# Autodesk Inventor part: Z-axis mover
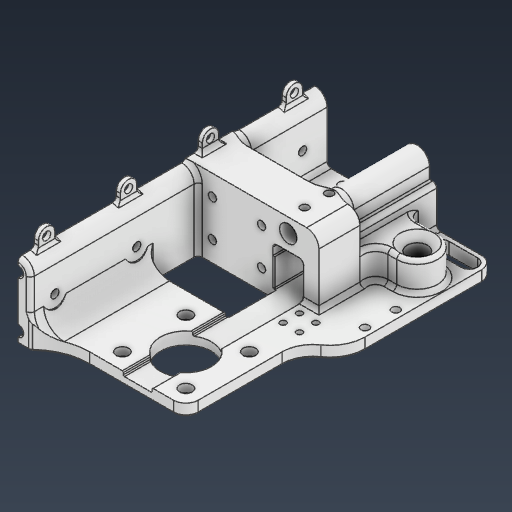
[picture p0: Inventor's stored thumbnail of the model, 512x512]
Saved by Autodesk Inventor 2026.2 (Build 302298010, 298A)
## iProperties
Created: 2026-04
Part Number: Z-axis mover
Material: ABS 플라스틱
Document SubType Name: Modeling
Designer: work
Density: 1.06 g/cm^3
Appearance: 매끄러움 - 흰색
Mass: 127.398 g
Surface Area: 474.299 cm^2
Volume: 120.186 cm^3
Author: work
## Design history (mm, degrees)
sketch "스케치1"
  geometry: L1 (0, 0)-(8, 0); L2 (0, 0)-(0, 8); L3 (0, 0)-(-8, 0); L4 (0, 0)-(0, -8); L5 (0, 0)-(50, 0); L6 (0, 0)-(-50, 0); L7 (0, 0)-(0, 50); L8 (25, 0)-(25, -380); L9 (-25, 0)-(-25, -380); L10 (-25, 0)-(-25, 70); L11 (25, -380)-(-25, -380); L12 (25, 0)-(25, 0); L13 (25, 0)-(25, 120); L14 (-37.5, -395)-(37.5, -395); L15 (37.5, -395)-(37.5, -365); L16 (37.5, -365)-(-37.5, -365); L17 (-37.5, -365)-(-37.5, -395); L18 (-37.5, -395)-(37.5, -365); L19 (37.5, -395)-(-37.5, -365); L20 (-62.5, 38)-(62.5, 38); L21 (62.5, 38)-(62.5, -38); L22 (62.5, -38)-(-62.5, -38); L23 (-62.5, -38)-(-62.5, 38); L24 (-62.5, 38)-(62.5, -38); L25 (62.5, 38)-(-62.5, -38); L26 (62.5, -25)-(-62.5, -25); L27 (17, 38)-(-17, 38); L28 (-17, 38)-(-17, 61); L29 (-17, 61)-(17, 61); L30 (17, 61)-(17, 38); L31 (-22, 60.236)-(-22, 100); L32 (-22, 100)-(-28, 100); L33 (-28, 100)-(-28, -380); L34 (-28, -380)-(-22, -380); L35 (-22, -380)-(-22, 100); L36 (-40, 38)-(40, 38); L37 (40, 38)-(40, 18); L38 (40, 18)-(-40, 18); L39 (-40, 18)-(-40, 38); C1 r 5.25 at (0, 0); C2 r 11.3 at (0, 0); C3 r 2 at (8, 0); C4 r 2 at (0, 8); C5 r 2 at (-8, 0); C6 r 2 at (0, -8); C7 r 4.4 at (50, 0); C8 r 4.4 at (-50, 0); C9 r 4 at (0, 50); 7 further points
  constraints: 78 end point, 12 midpoint, 10 parallel, 9 centre point, 9 coincident, 8 horizontal, 6 perpendicular, 6 point on line, 5 vertical, 2 symmetric about line, 1 collinear, 22 other
  dimensions: "d0" = 10.5 diameter of C1; "d1" = 22.6 diameter of C2; "d2" = 8 distance of L1.start L1.end; "d3" = 4 diameter of C3; "d6" = 360 deg dimension on C1.centre L1.end (derived); "d8" = 50 distance of L4.start L5.end; "d9" = 8.8 diameter of C7; "d10" = 50 distance of L4.start L7.end; "d11" = 8 diameter of C9; "d12" = 12 distance of point (0, 38) L7.end; "d15" = 450 distance of L9.end L10.end; "d16" = 25 distance from line of point (0, 0) L8; "d17" = 25 distance from line of L10 C1.centre; "d19" = 500 distance of L8.end L13.end; "d20" = 120 vertical distance of point (0, 0) L13.end; "d21" = 75 distance between parallel lines of L17 L15; "d22" = 30 distance of L14.end L15.end; "d23" = 125 distance between parallel lines of L23 L21; "d24" = 25 distance from line of point (0, 0) L26; "d25" = 340 distance between parallel lines of L16 L26 (derived); "d26" = 34 distance of L28.end L29.end; "d27" = 23 distance of L27.end L28.end; "d30" = 6 distance between parallel lines of L33 L35; "d31" = 80 distance of L37.end L38.end; "d32" = 20 distance of L36.end L37.end; "d60" = 30 distance of L10.end point (-25, 100)
  node "스케치 - 원형 패턴1" dims "d6" = 360 deg (derived)
extrude "돌출1" new body sketch "스케치1" distance "d33" = 6; taper "d34" = 0 deg
extrude "돌출2" join sketch "스케치1" distance "d35" = 4; taper "d36" = 0 deg
extrude "돌출3" join sketch "스케치1" distance "d37" = 38; taper "d38" = 0 deg
sketch "스케치2"
  geometry: L1 (102.5, 6)-(22.5, 6) reference; L2 (87.5, 6)-(87.5, 31); L3 (93.5, 6)-(93.5, 31); L4 (81.5, 31)-(81.5, 6); L5 (0, 0)-(125, 0) reference; L6 (62.5, 6)-(37.5, 6); L7 (37.5, 6)-(37.5, 31); L8 (37.5, 31)-(62.5, 31); L9 (62.5, 31)-(62.5, 6); L10 (30.5, 4)-(44.5, 4); L11 (44.5, 4)-(44.5, 18); L12 (44.5, 18)-(30.5, 18); L13 (30.5, 18)-(30.5, 4); L14 (30.5, 4)-(44.5, 18); L15 (44.5, 4)-(30.5, 18); L16 (44.5, -10.5)-(86.5, -10.5); L17 (86.5, -10.5)-(86.5, 32.5); L18 (86.5, 32.5)-(44.5, 32.5); L19 (44.5, 32.5)-(44.5, -10.5); L20 (44.5, -10.5)-(86.5, 32.5); L21 (86.5, -10.5)-(44.5, 32.5); L22 (47.5, 32.5)-(47.5, -10.5); L23 (37.5, 6)-(37.5, 31); L24 (43.5, 6)-(43.5, 31); L25 (31.5, 31)-(31.5, 6); L26 (47, 1.5)-(28, 1.5); L27 (28, 1.5)-(28, 20.5); L28 (28, 20.5)-(47, 20.5); L29 (47, 20.5)-(47, 1.5); L30 (47, 1.5)-(28, 20.5); L31 (28, 1.5)-(47, 20.5); C1 r 2.75 at (87.5, 6); C2 r 2.75 at (87.5, 31); C3 r 4.25 at (37.5, 31); A1 r 6 centre (87.5, 6) between (81.5, 6) and (93.5, 6); A2 r 6 centre (87.5, 31) between (93.5, 31) and (81.5, 31); A3 r 6 centre (37.5, 6) between (31.5, 6) and (43.5, 6); A4 r 6 centre (37.5, 31) between (43.5, 31) and (31.5, 31); 16 further points
  constraints: 62 end point, 11 midpoint, 10 parallel, 10 tangent, 8 point on circle, 7 centre point, 7 perpendicular, 5 point on line, 4 horizontal, 2 coincident
  dimensions: "d39" = 5.5 diameter of C1; "d40" = 25 distance of L2.start L6.start; "d41" = 25 distance of L2.start L2.end; "d42" = 5.5 diameter of C2; "d43" = 25 distance of L7.end L8.end; "d44" = 25 distance of L6.end L7.end; "d45" = 8.5 diameter of C3; "d46" = 14 distance of L11.end L12.end; "d47" = 14 distance of L10.end L11.end; "d48" = 43 distance of L16.end L17.end; "d50" = 20 distance of L7.end point (37.5, 11); "d51" = 39 distance between parallel lines of L17 L22; "d52" = 3 distance between parallel lines of L22 L19; "d59" = 2.5 distance between parallel lines of L28 L12
extrude "돌출4" join sketch "스케치2" distance "d53" = 145; taper "d54" = 0 deg
extrude "돌출5" cut sketch "스케치2" extent not by distance; stored distance "d55" = 10; taper "d56" = 0 deg
sketch "스케치3"
  geometry: L1 (-31.5, 20.5)-(-31.5, 31) reference; L2 (-43.5, 31)-(-43.5, 20.5) reference; L3 (-30.5, 4)-(-44.5, 4) reference; L4 (-44.5, 18)-(-30.5, 18) reference; L5 (-28, 20.5)-(-31.5, 20.5) reference; L6 (-43.5, 20.5)-(-47, 20.5) reference; L7 (-47, 1.5)-(-41.469, 1.5) reference; L8 (-33.531, 1.5)-(-28, 1.5) reference; L9 (-28, 1.5)-(-28, 20.5) reference; L10 (-30.5, 18)-(-30.5, 4) reference; L11 (-44.5, 4)-(-44.5, 18) reference; L12 (-47, 20.5)-(-47, 1.5) reference; C1 r 6 at (-37.5, 31); A1 r 6 centre (-37.5, 6) between (-41.469, 1.5) and (-33.531, 1.5) reference; A2 r 6 centre (-37.5, 31) between (-31.5, 31) and (-43.5, 31) reference; 5 further points
  constraints: 1 centre point, 1 concentric
extrude "돌출6" cut sketch "스케치3" stored distance "d57" = 145; taper "d58" = 0 deg
sketch "스케치5"
  geometry: L1 (29.25, 38)-(20.75, 38) reference; L2 (18, 38)-(32, 38) reference; L3 (32, 38)-(18, 38) reference; L4 (-25, 38)-(62.5, 38) reference; L5 (40, 38)-(62.5, 38) reference; L6 (-40, 38)-(40, 38) reference; L7 (-62.5, 38)-(-40, 38) reference; L8 (-62.5, 38)-(-25, 38) reference; L9 (-25, 38)-(-31, 38) reference; L10 (-31, 38)-(-19, 38) reference; L11 (-19, 38)-(-25, 38) reference; L12 (25, 38)-(25, 88); L13 (9.5, 103.5)-(40.5, 103.5); L14 (40.5, 103.5)-(40.5, 72.5); L15 (40.5, 72.5)-(9.5, 72.5); L16 (9.5, 72.5)-(9.5, 103.5); L17 (9.5, 103.5)-(40.5, 72.5); L18 (40.5, 103.5)-(9.5, 72.5); L19 (1.5, 111.5)-(48.5, 111.5); L20 (48.5, 111.5)-(48.5, 64.5); L21 (48.5, 64.5)-(1.5, 64.5); L22 (1.5, 64.5)-(1.5, 111.5); L23 (1.5, 111.5)-(48.5, 64.5); L24 (48.5, 111.5)-(1.5, 64.5); L25 (-22.25, 120)-(-22.25, -25) reference; L26 (-31, 38)-(-19, 38) reference; L27 (-31, 38)-(-31, 120) reference; L28 (-19, 120)-(-31, 120) reference; L29 (-19, 38)-(-19, 120) reference; L30 (62.5, 38)-(62.5, -25) reference; L31 (40, 18)-(40, 38) reference; L32 (-62.5, 38)-(-25, 38) reference; L33 (-62.5, -25)-(-62.5, 38) reference; L34 (62.5, -25)-(-62.5, -25) reference; L35 (62.5, 38)-(62.5, -25) reference; L36 (-25, 38)-(62.5, 38) reference; L37 (-19, 38)-(19, 38); L38 (19, 38)-(19, 62); L39 (19, 62)-(-19, 62); L40 (-19, 62)-(-19, 38); L41 (-19, 38)-(-19, 120) reference; C1 r 12.5 at (25, 88); C2 r 2 at (9.5, 72.5); C3 r 2 at (40.5, 103.5); C4 r 2 at (9.5, 103.5); C5 r 2 at (40.5, 72.5); C6 r 2 at (0, -8) reference; C7 r 2 at (8, 0) reference; C8 r 2 at (0, 8) reference; C9 r 2 at (-8, 0) reference; C10 r 5.25 at (0, 0) reference; C11 r 4.4 at (50, 0) reference; C12 r 4.4 at (-50, 0) reference; A1 r 28.971 centre (1.5, 140.471) between (-19, 120) and (1.5, 111.5); A2 r 15 centre (63.5, 64.5) between (48.5, 64.5) and (55.046, 52.109); A3 r 17.08 centre (45.42, 38) between (62.5, 38) and (55.046, 52.109); 15 further points
  constraints: 34 end point, 8 centre point, 6 parallel, 6 point on circle, 5 coincident, 5 midpoint, 4 perpendicular, 4 tangent, 3 horizontal, 2 point on line, 5 other
  dimensions: "d61" = 25 distance from line of point (0, 38) L12; "d62" = 25 diameter of C1; "d63" = 31 distance of L14.end L15.end; "d64" = 31 distance of L13.end L14.end; "d65" = 4 diameter of C2; "d66" = 4 diameter of C3; "d67" = 4 diameter of C4; "d68" = 4 diameter of C5; "d69" = 50 distance of L12.start L12.end; "d70" = 8 distance between parallel lines of L14 L20; "d71" = 15 radius of A2; "d73" = 24 distance of L39.end L37.start
extrude "돌출7" join sketch "스케치5" distance "d74" = 6; taper "d75" = 0 deg
sketch "스케치6"
  geometry: L1 (-81.5, 31)-(-81.5, 0) reference; L2 (-81.5, 0)-(-43.5, 0) reference; L3 (-43.5, 0)-(-43.5, 4) reference; L4 (-30.5, 6)-(-22.5, 6) reference; L5 (-44.5, 18)-(-44.5, 4) reference; L6 (-30.5, 18)-(-44.5, 18) reference; L7 (-30.5, 6)-(-30.5, 18) reference; L8 (-22.5, 6)-(-22.5, 38) reference; L9 (-102.5, 38)-(-22.5, 38) reference; L10 (-102.5, 6)-(-102.5, 38) reference; L11 (-125, 6)-(-102.5, 6) reference; L12 (-125, 0)-(-125, 6) reference; L13 (-125, 0)-(-93.5, 0) reference; L14 (-93.5, 0)-(-93.5, 31) reference; L15 (-81.5, 6)-(-81.5, 31) reference; L16 (-93.5, 31)-(-93.5, 0) reference; L17 (0, 0)-(-125, 0) reference; L18 (-93.5, 6)-(-81.5, 6); L19 (-81.5, 6)-(-81.5, 0); L20 (-81.5, 0)-(-93.5, 0); L21 (-93.5, 0)-(-93.5, 6); L22 (-81.5, 0)-(-93.5, 0) reference; L23 (-81.5, 0)-(-81.5, 6) reference; L24 (-90.25, 6)-(-84.75, 6) reference; L25 (-44.5, 4)-(-43.5, 4) reference; C1 r 4.25 at (-37.5, 31) reference; C2 r 2.75 at (-87.5, 31) reference; A1 r 6 centre (-87.5, 31) between (-81.5, 31) and (-93.5, 31) reference; A2 r 6 centre (-87.5, 31) between (-81.5, 31) and (-93.5, 31) reference; A3 r 2.75 centre (-87.5, 6) between (-84.75, 6) and (-90.25, 6) reference; 10 further points
  constraints: 8 end point, 2 parallel, 2 point on line, 1 horizontal, 1 perpendicular
extrude "돌출8" join sketch "스케치6" stored distance "d76" = 6; taper "d77" = 0 deg
sketch "스케치7"
  geometry: L1 (47, 6)-(81.5, 6) reference; L2 (47, 20.5)-(43.5, 20.5) reference; L3 (43.5, 20.5)-(43.5, 31) reference; L4 (31.5, 31)-(31.5, 20.5) reference; L5 (31.5, 20.5)-(28, 20.5) reference; L6 (28, 20.5)-(28, 6) reference; L7 (0, 6)-(28, 6) reference; L8 (0, 0)-(0, 6) reference; L9 (0, 0)-(125, 0) reference; L10 (125, 0)-(125, 6) reference; L11 (93.5, 6)-(125, 6) reference; L12 (93.5, 6)-(93.5, 31) reference; L13 (81.5, 31)-(81.5, 6) reference; L14 (44.5, 18)-(44.5, 4) reference; L15 (44.5, 4)-(30.5, 4) reference; L16 (30.5, 4)-(30.5, 18) reference; L17 (30.5, 18)-(44.5, 18) reference; L18 (43.5, 4)-(30.5, 4) reference; L19 (43.5, 4)-(43.5, 6) reference; L20 (30.5, 6)-(43.5, 6) reference; L21 (30.5, 4)-(30.5, 6) reference; L22 (81.5, 0)-(43.5, 0) reference; L23 (81.5, 0)-(81.5, 6) reference; L24 (43.5, 6)-(81.5, 6) reference; L25 (43.5, 0)-(43.5, 6) reference; L26 (47, 6)-(47, 20.5) reference; C1 r 2.75 at (87.5, 31) reference; C2 r 2.75 at (87.5, 6) reference; C3 r 2.75 at (87.5, 31) reference; A1 r 6 centre (37.5, 31) between (43.5, 31) and (31.5, 31) reference; A2 r 6 centre (87.5, 31) between (93.5, 31) and (81.5, 31) reference; 4 further points
extrude "돌출9" cut sketch "스케치7" extent not by distance; stored distance "d78" = 0; taper "d79" = 0 deg
sketch "스케치8"
  geometry: L1 (50.5, 10)-(74.5, 10); L2 (74.5, 10)-(74.5, 28); L3 (74.5, 28)-(50.5, 28); L4 (50.5, 28)-(50.5, 10); L5 (50.5, 10)-(74.5, 28); L6 (74.5, 10)-(50.5, 28); L7 (102.5, 38)-(22.5, 38) reference; L8 (62.5, 38)-(62.5, 0); C1 r 2 at (50.5, 28); C2 r 2 at (50.5, 10); C3 r 2 at (74.5, 10); C4 r 2 at (74.5, 28); 1 further point
  constraints: 14 end point, 4 centre point, 4 coincident, 4 midpoint, 2 parallel, 1 horizontal, 1 perpendicular, 1 vertical
  dimensions: "d80" = 24 distance of L3.end L2.end; "d81" = 18 distance of L2.end L1.end; "d82" = 4 diameter of C1; "d83" = 4 diameter of C2; "d84" = 4 diameter of C3; "d85" = 4 diameter of C4
extrude "돌출10" cut sketch "스케치8" extent not by distance; stored distance "d86" = 18 (derived); taper "d87" = 0 deg
sketch "스케치9"
  geometry: L1 (59, -32)-(59, -7) reference; L2 (71, -7)-(71, -32) reference; L3 (80, -32)-(71, -32) reference; L4 (80, -32)-(80, 0) reference; L5 (0, 0)-(80, 0) reference; L6 (0, -32)-(0, 0) reference; L7 (5.5, -32)-(0, -32) reference; L8 (5.5, -32)-(5.5, -17.5) reference; L9 (5.5, -17.5)-(9, -17.5) reference; L10 (9, -17.5)-(9, -7) reference; L11 (21, -7)-(21, -17.5) reference; L12 (21, -17.5)-(24.5, -17.5) reference; L13 (59, -32)-(24.5, -32) reference; L14 (24.5, -17.5)-(24.5, -32) reference; C1 r 2 at (28, -28) reference; C2 r 2 at (52, -28) reference; C3 r 2 at (28, -10) reference; C4 r 2 at (52, -10) reference; C5 r 2 at (52, -28) reference; A1 r 6 centre (65, -7) between (71, -7) and (59, -7) reference; A2 r 6 centre (15, -7) between (21, -7) and (9, -7) reference; 5 further points
  constraints: 4 coincident
hole "구멍1" sketch "스케치9" at (52, -10), (28, -10), (28, -28), (52, -28) diameter "d88" = 4; stored, may be unused: countersink angle "d92" = 90 deg, drill point angle "d94" = 0 deg; dims "d89" = 6, "d90" = 6.2, "d91" = 4, "d93" = 8
sketch "스케치10"
  geometry: L1 (32, -98.356)-(32, -111.5) reference; L2 (32, -111.5)-(48.5, -111.5) reference; L3 (48.5, -111.5)-(48.5, -64.5) reference; L4 (62.5, -38)-(62.5, 25) reference; L5 (62.5, 25)-(34.5, 25) reference; L6 (34.5, 25)-(34.5, -18) reference; L7 (34.5, -18)-(40, -18) reference; L8 (40, -18)-(40, -38) reference; L9 (32, -38)-(40, -38) reference; L10 (32, -38)-(32, -77.644) reference; L11 (-31, -18)-(-31, 25) reference; L12 (-31, 25)-(-62.5, 25) reference; L13 (-62.5, 25)-(-62.5, -38) reference; L14 (-62.5, -38)-(-40, -38) reference; L15 (-40, -38)-(-40, -18) reference; L16 (-40, -18)-(-31, -18) reference; L17 (-50, -10)-(-31, -10); L18 (-50, 10)-(-31, 10); L19 (50, 10)-(34.5, 10); L20 (50, -10)-(34.5, -10); C1 r 4.4 at (50, 0) reference; C2 r 2 at (40.5, -72.5) reference; C3 r 2 at (40.5, -103.5) reference; C4 r 4.4 at (-50, 0) reference; A1 r 15 centre (63.5, -64.5) between (55.046, -52.109) and (48.5, -64.5) reference; A2 r 17.08 centre (45.42, -38) between (55.046, -52.109) and (62.5, -38) reference; A3 r 12.5 centre (25, -88) between (32, -98.356) and (32, -77.644) reference; A4 r 10 centre (-50, 0) between (-50, -10) and (-50, 10); A5 r 10 centre (50, 0) between (50, 10) and (50, -10); 1 further point
  constraints: 8 end point, 4 perpendicular, 4 point on circle, 4 point on line, 4 tangent, 2 centre point, 2 coincident
  dimensions: "d95" = 20 diameter of A4; "d96" = 20 diameter of A5
extrude "돌출11" join sketch "스케치10" stored distance "d97" = 10; taper "d98" = 0 deg
fillet "모깎기1" dims "d99" = 6
sketch "스케치11"
  geometry: C1 r 4.25 at (0, 0) reference; 1 further point
extrude "돌출12" cut sketch "스케치11" extent not by distance; stored distance "d100" = 0; taper "d101" = 0 deg
fillet "모깎기2" dims "d102" = 2
fillet "모깎기3" dims "d103" = 0.5
chamfer "모따기1" distance "d104" = 1; stored, may be unused: second distance "d105" = 2, angle "d106" = 45 deg
sketch "스케치12" dims "d0" = 10.5, "d1" = 22.6, "d2" = 8, "d3" = 4, "d6" = 360 deg (derived), "d8" = 50, "d9" = 8.8, "d10" = 50, "d11" = 8, "d12" = 12, "d15" = 450, "d16" = 25, "d17" = 25, "d19" = 500, "d20" = 120, "d21" = 75, "d22" = 30, "d23" = 125, "d24" = 25, "d25" = 340 (derived), "d26" = 34, "d27" = 23, "d30" = 6, "d31" = 80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
  geometry: L1 (17.5, -61.936)-(17.5, -78) reference; L2 (17, -62)-(-17, -62) reference; L3 (-19, -60)-(-19, -118) reference; L4 (-21, -120)-(-19.813, -120) reference; L5 (1.5, -111.5)-(17.5, -111.5) reference; L6 (17.5, -98)-(17.5, -111.5) reference; L7 (42, -40)-(42, -17.621) reference; L8 (32.5, -78)-(32.5, -40) reference; L9 (32.5, -111.5)-(32.5, -98) reference; L10 (32.5, -111.5)-(42.5, -111.5) reference; L11 (48.5, -105.5)-(48.5, -64.5) reference; L12 (62.5, -38)-(62.5, 19) reference; L13 (56.5, 25)-(36.5, 25) reference; L14 (36.5, 16)-(36.5, 25) reference; L15 (50, 12)-(40.5, 12) reference; L16 (45.657, -12)-(50, -12) reference; L17 (42, -40)-(42, -17.621) reference; L18 (32.5, -40)-(42, -40) reference; C1 r 2 at (9.5, -72.5) reference; C2 r 2 at (9.5, -103.5) reference; C3 r 2 at (40.5, -103.5) reference; C4 r 2 at (40.5, -72.5) reference; C5 r 2 at (40.5, -103.5) reference; A1 r 2 centre (17, -60) between (17, -62) and (17.5, -61.936) reference; A2 r 2 centre (-17, -60) between (-19, -60) and (-17, -62) reference; A3 r 2 centre (-21, -118) between (-21, -120) and (-19, -118) reference; A4 r 2 centre (-19.813, -118) between (-19.813, -120) and (-18.437, -119.451) reference; A5 r 28.971 centre (1.5, -140.471) between (1.5, -111.5) and (-18.437, -119.451) reference; A6 r 12.5 centre (25, -88) between (17.5, -78) and (17.5, -98) reference; A7 r 12.5 centre (25, -88) between (32.5, -98) and (32.5, -78) reference; A8 r 6 centre (42.5, -105.5) between (42.5, -111.5) and (48.5, -105.5) reference; A9 r 15 centre (63.5, -64.5) between (55.046, -52.109) and (48.5, -64.5) reference; A10 r 17.08 centre (45.42, -38) between (55.046, -52.109) and (62.5, -38) reference; A11 r 6 centre (56.5, 19) between (62.5, 19) and (56.5, 25) reference; A12 r 4 centre (40.5, 16) between (36.5, 16) and (40.5, 12) reference; A13 r 12 centre (50, 0) between (50, -12) and (50, 12) reference; A14 r 4 centre (45.657, -16) between (45.657, -12) and (42, -17.621) reference; 5 further points
  constraints: 4 coincident
hole "구멍2" sketch "스케치12" at (9.5, -103.5), (40.5, -103.5), (40.5, -72.5), (9.5, -72.5) diameter "d107" = 4; stored, may be unused: countersink angle "d111" = 90 deg, drill point angle "d113" = 0 deg; dims "d6" = 360 deg (derived), "d25" = 340 (derived), "d108" = 6, "d109" = 6.2, "d110" = 4, "d112" = 8
fillet "모깎기4" dims "d114" = 10
sketch "스케치13"
  geometry: L1 (78, -30)-(0, -30) reference; L2 (78, 0)-(78, -30) reference; L3 (0, 0)-(78, 0) reference; L4 (0, -30)-(0, 0) reference; L5 (68, 0)-(28, 0); L6 (28, 0)-(28, -25); L7 (28, -25)-(68, -25); L8 (68, -25)-(68, 0); C1 r 4 at (28, 0); C2 r 4 at (28, -25); C3 r 4 at (68, -25); C4 r 4 at (68, 0); 1 further point
  constraints: 8 end point, 4 centre point, 2 parallel, 1 coincident, 1 horizontal, 1 perpendicular, 1 point on line
  dimensions: "d115" = 40 distance of L7.end L6.end; "d116" = 25 distance of L6.end L5.end; "d117" = 10 distance between parallel lines of L2 L8; "d118" = 8 diameter of C1; "d119" = 8 diameter of C2; "d120" = 8 diameter of C3; "d121" = 8 diameter of C4
  node "투영된 루프17"
extrude "돌출13" join sketch "스케치13" stored distance "d122" = 8 (derived); taper "d123" = 0 deg
extrude "돌출14" join sketch "스케치13" distance "d124" = 1.5; taper "d125" = 0 deg
sketch "스케치14"
  geometry: L1 (4, 0)-(36, 0) reference; L2 (-28, 0)-(-4, 0) reference; L3 (-28, -30)-(-28, 0) reference; L4 (50, -30)-(-28, -30) reference; L5 (50, 0)-(50, -30) reference; L6 (44, 0)-(50, 0) reference; C1 r 4 at (40, -25) reference; C2 r 4 at (0, -25) reference; C3 r 2 at (0, 0); C4 r 2 at (0, -25); C5 r 2 at (40, -25); C6 r 2 at (40, 0); A1 r 4 centre (40, 0) between (36, 0) and (44, 0) reference; A2 r 4 centre (0, 0) between (-4, 0) and (4, 0) reference; 1 further point
  constraints: 4 centre point, 4 coincident
  dimensions: "d126" = 4 diameter of C3; "d127" = 4 diameter of C4; "d128" = 4 diameter of C5; "d129" = 4 diameter of C6
  node "투영된 루프18"
extrude "돌출15" cut sketch "스케치14" stored distance "d130" = 1.5; taper "d131" = 0 deg
extrude "돌출16" cut sketch "스케치14" stored distance "d132" = 10; taper "d133" = 0 deg
fillet "모깎기5" dims "d134" = 2
sketch "스케치15"
  geometry: L1 (-21.127, -38)-(34, -38) reference; L2 (25, -38)-(25, -18); C1 r 2 at (25, -18); C2 r 2 at (25, -30); 1 further point
  constraints: 2 centre point, 2 end point, 2 point on line, 1 coincident, 1 vertical
  dimensions: "d135" = 20 distance of L2.start L2.end; "d136" = 25 distance from line of L2 point (0, 0); "d137" = 4 diameter of C1; "d138" = 4 diameter of C2; "d139" = 12 distance of L2.end C2.centre
extrude "돌출17" cut sketch "스케치15" stored distance "d140" = 10; taper "d141" = 0 deg; dims "d9" = 8.8
sketch "스케치16" dims "d145" = 7
  geometry: L1 (13, -21.5)-(13, -1.9); L2 (8, -25)-(31.5, -25) reference; L3 (6, -23)-(6, 0) reference; L4 (13, -5.4)-(6, -5.4); L5 (13, 1.6)-(5.783, 1.6); L6 (13, -18)-(6, -18); L7 (-42.5, -26.5)-(-42.5, -13.5) reference; L8 (-56.5, -27.5)-(-43.5, -27.5) reference; L9 (-57.5, -13.5)-(-57.5, -26.5) reference; L10 (-43.5, -12.5)-(-56.5, -12.5) reference; L11 (31.5, -30)-(-81.5, -30) reference; L12 (31.5, -25)-(31.5, -30) reference; L13 (8, -25)-(31.5, -25) reference; L14 (6, -23)-(6, 0) reference; L15 (-6, 0)-(-6, -23) reference; L16 (-38.5, -25)-(-8, -25) reference; L17 (-40.5, -23)-(-40.5, -12.5) reference; L18 (-42.5, -10.5)-(-44, -10.5) reference; L19 (-44, -10.5)-(-44, 0) reference; L20 (-56, 0)-(-56, -10.5) reference; L21 (-56, -10.5)-(-57.5, -10.5) reference; L22 (-59.5, -12.5)-(-59.5, -23) reference; L23 (-81.5, -25)-(-61.5, -25) reference; L24 (-81.5, -30)-(-81.5, -25) reference; C1 r 2 at (13, -21.5); C2 r 2 at (13, -1.9); C3 r 4.25 at (-50, 0) reference; C4 r 2.75 at (0, 0) reference; C5 r 2.75 at (0, -25) reference; A1 r 3.5 centre (13, -1.9) between (13, -5.4) and (13, 1.6); A2 r 6 centre (0, 0) between (6, 0) and (-6, 0) reference; A3 r 1 centre (-43.5, -13.5) between (-42.5, -13.5) and (-43.5, -12.5) reference; A4 r 1 centre (-43.5, -26.5) between (-43.5, -27.5) and (-42.5, -26.5) reference; A5 r 1 centre (-56.5, -26.5) between (-57.5, -26.5) and (-56.5, -27.5) reference; A6 r 1 centre (-56.5, -13.5) between (-56.5, -12.5) and (-57.5, -13.5) reference; A7 r 2 centre (8, -23) between (6, -23) and (8, -25) reference; A8 r 6 centre (0, 0) between (6, 0) and (-6, 0) reference; A9 r 2 centre (-8, -23) between (-8, -25) and (-6, -23) reference; A10 r 2 centre (-38.5, -23) between (-40.5, -23) and (-38.5, -25) reference; A11 r 2 centre (-42.5, -12.5) between (-40.5, -12.5) and (-42.5, -10.5) reference; A12 r 6 centre (-50, 0) between (-44, 0) and (-56, 0) reference; A13 r 2 centre (-57.5, -12.5) between (-57.5, -10.5) and (-59.5, -12.5) reference; A14 r 2 centre (-61.5, -23) between (-61.5, -25) and (-59.5, -23) reference; 5 further points
  constraints: 8 end point, 4 point on line, 3 centre point, 3 coincident, 3 perpendicular, 3 point on circle, 2 horizontal, 1 tangent, 1 vertical, 3 other
  dimensions: "d142" = 4 diameter of C1; "d143" = 4 diameter of C2; "d144" = 7 diameter of A1; "d146" = 19.6 distance of L1.start L1.end; "d147" = 7 distance from line of L3 L1.start
extrude "돌출18" join sketch "스케치16" distance "d148" = 3; taper "d149" = 0 deg
fillet "모깎기6" dims "d150" = 1
sketch "스케치17"
  geometry: L1 (0, 0)-(0, 25); L2 (13.5, 25)-(-17, 25) reference; L3 (7.5, 21)-(-7.5, 21); L4 (58.5, -34)-(58.5, -19); L5 (62.5, -38)-(62.5, 19) reference; C1 r 2 at (-7.5, 21); C2 r 2 at (7.5, 21); C3 r 2 at (58.5, -34); C4 r 2 at (58.5, -19); 1 further point
  constraints: 6 end point, 4 centre point, 4 coincident, 2 point on line, 2 vertical, 1 horizontal, 1 midpoint
  dimensions: "d151" = 15 distance of L3.start L3.end; "d152" = 4 diameter of C1; "d153" = 4 diameter of C2; "d154" = 4 distance between parallel lines of L2 L3; "d155" = 15 distance of L4.start L4.end; "d156" = 4 diameter of C3; "d157" = 4 diameter of C4; "d158" = 4 distance between parallel lines of L5 L4; "d159" = 4 horizontal distance of L5.start L4.start
extrude "돌출19" cut sketch "스케치17" extent not by distance; stored distance "d160" = 0; taper "d161" = 0 deg
sketch "스케치18"
  geometry: L1 (-42, -17.621)-(-42, -38) reference; L2 (-50, -12)-(-45.657, -12) reference; C1 r 16 at (-60, -30); 1 further point
  constraints: 1 centre point
  dimensions: "d162" = 32 diameter of C1; "d163" = 2 distance edge to line of C1 L1; "d164" = 2 distance edge to line of C1 L2
extrude "돌출20" cut sketch "스케치18" distance "d165" = 2; taper "d166" = 0 deg
sketch "스케치19"
  geometry: L1 (56.5, 19)-(42.5, 19); L2 (56.5, 23)-(42.5, 23); L3 (42.5, 15)-(56.5, 15); L4 (36.5, 16)-(36.5, 25) reference; L5 (-56.5, 19)-(-48, 19); L6 (-56.5, 15)-(-48, 15); L7 (-48, 23)-(-56.5, 23); L8 (-46.144, -38)-(-42, -38) reference; L9 (-42, -17.621)-(-42, -38) reference; L10 (-50, -12)-(-45.657, -12) reference; L11 (-37, 12)-(-50, 12) reference; L12 (-33, 21)-(-33, 16) reference; L13 (-41.742, 21)-(-33, 21) reference; L14 (-41.742, 25)-(-56.5, 25) reference; L15 (-62.5, 19)-(-62.5, -14.197) reference; L16 (36.5, -52)-(44.5, -52); L17 (44.5, -52)-(44.5, -44); L18 (44.5, -44)-(36.5, -44); L19 (36.5, -44)-(36.5, -52); L20 (32.5, -40)-(42, -40) reference; L21 (32.5, -78)-(32.5, -40) reference; L22 (13.5, 25)-(13.5, -16.011) reference; L23 (13.5, 25)-(-17, 25) reference; L24 (-17, -12)-(-17, 25) reference; L25 (9.631, -16)-(-9.631, -16) reference; L26 (32.5, -78)-(32.5, -40) reference; L27 (32.5, -111.5)-(32.5, -98) reference; L28 (32.5, -111.5)-(42.5, -111.5) reference; L29 (48.5, -105.5)-(48.5, -64.5) reference; L30 (62.5, -38)-(62.5, 19) reference; L31 (56.5, 25)-(36.5, 25) reference; L32 (36.5, 16)-(36.5, 25) reference; L33 (50, 12)-(40.5, 12) reference; L34 (45.657, -12)-(50, -12) reference; L35 (42, -40)-(42, -17.621) reference; L36 (32.5, -40)-(42, -40) reference; L37 (-41.742, 25)-(-41.742, 21) reference; C1 r 1.5 at (36.5, -52); C2 r 1.5 at (36.5, -44); C3 r 1.5 at (44.5, -44); C4 r 1.5 at (44.5, -52); A1 r 4 centre (56.5, 19) between (56.5, 15) and (56.5, 23); A2 r 4 centre (42.5, 19) between (42.5, 23) and (42.5, 15); A3 r 6 centre (56.5, 19) between (62.5, 19) and (56.5, 25) reference; A4 r 4 centre (-56.5, 19) between (-56.5, 23) and (-56.5, 15); A5 r 4 centre (-48, 19) between (-48, 15) and (-48, 23); A6 r 6 centre (-56.5, 19) between (-56.5, 25) and (-62.5, 19) reference; A7 r 16 centre (-60, -30) between (-46.144, -38) and (-62.5, -14.197) reference; A8 r 4 centre (-45.657, -16) between (-42, -17.621) and (-45.657, -12) reference; A9 r 12 centre (-50, 0) between (-50, 12) and (-50, -12) reference; A10 r 4 centre (-37, 16) between (-37, 12) and (-33, 16) reference; A11 r 6 centre (-56.5, 19) between (-56.5, 25) and (-62.5, 19) reference; A12 r 4 centre (-13, -12) between (-17, -12) and (-13.912, -15.895) reference; A13 r 12.5 centre (25, -88) between (32.5, -98) and (32.5, -78) reference; A14 r 6 centre (42.5, -105.5) between (42.5, -111.5) and (48.5, -105.5) reference; A15 r 15 centre (63.5, -64.5) between (55.046, -52.109) and (48.5, -64.5) reference; A16 r 17.08 centre (45.42, -38) between (55.046, -52.109) and (62.5, -38) reference; A17 r 6 centre (56.5, 19) between (62.5, 19) and (56.5, 25) reference; A18 r 4 centre (40.5, 16) between (36.5, 16) and (40.5, 12) reference; A19 r 12 centre (50, 0) between (50, -12) and (50, 12) reference; A20 r 4 centre (45.657, -16) between (45.657, -12) and (42, -17.621) reference; 8 further points
  constraints: 24 end point, 10 point on circle, 8 centre point, 8 tangent, 4 coincident, 4 parallel, 3 horizontal, 3 midpoint, 2 concentric, 1 perpendicular, 4 other
  dimensions: "d167" = 8 diameter of A2; "d168" = 2 distance from line of point (38.5, 19) L4; "d169" = 8 diameter of A5; "d171" = 3 diameter of C1; "d172" = 3 diameter of C2; "d173" = 3 diameter of C3; "d174" = 3 diameter of C4; "d175" = 8 distance of L16.end L17.end; "d176" = 8 distance of L17.end L18.end; "d177" = 4 distance between parallel lines of L20 L18; "d178" = 4 distance from line of L21 point (36.5, -48)
extrude "돌출21" cut sketch "스케치19" extent not by distance; stored distance "d179" = 0; taper "d180" = 0 deg
sketch "스케치20"
  geometry: 1 further point
sketch "스케치21"
  geometry: L1 (7.5, -26.5)-(7.5, -13.5) reference; L2 (-6.5, -27.5)-(6.5, -27.5) reference; L3 (-7.5, -13.5)-(-7.5, -26.5) reference; L4 (6.5, -12.5)-(-6.5, -12.5) reference; L5 (81.5, -30)-(-31.5, -30) reference; L6 (81.5, -25)-(81.5, -30) reference; L7 (66.742, -25)-(81.5, -25) reference; L8 (63, -18)-(57, -18) reference; L9 (56, -17)-(56, -6.4) reference; L10 (57, -5.4)-(63, -5.4) reference; L11 (63, 1.6)-(56.499, 1.6) reference; L12 (44, 0)-(44, -23) reference; L13 (11.5, -25)-(42, -25) reference; L14 (9.5, -23)-(9.5, -12.5) reference; L15 (7.5, -10.5)-(6, -10.5) reference; L16 (6, -10.5)-(6, 0) reference; L17 (-6, 0)-(-6, -10.5) reference; L18 (-6, -10.5)-(-7.5, -10.5) reference; L19 (-9.5, -12.5)-(-9.5, -23) reference; L20 (-31.5, -25)-(-11.5, -25) reference; L21 (-31.5, -30)-(-31.5, -25) reference; L22 (-9.5, -12.5)-(-9.5, -7.5); L23 (-7.5, -5.5)-(7.5, -5.5); L24 (9.5, -12.5)-(9.5, -7.5); L25 (7.5, -13.5)-(7.5, -7.5); L26 (7.5, -7.5)-(-7.5, -7.5); L27 (-7.5, -7.5)-(-7.5, -13.5); L28 (-9.5, -13.5)-(9.5, -13.5); C1 r 2 at (63, -1.9) reference; C2 r 2 at (63, -21.5) reference; C3 r 4.25 at (0, 0) reference; C4 r 2.75 at (50, 0) reference; C5 r 2.75 at (50, -25) reference; A1 r 1 centre (6.5, -13.5) between (7.5, -13.5) and (6.5, -12.5) reference; A2 r 1 centre (6.5, -26.5) between (6.5, -27.5) and (7.5, -26.5) reference; A3 r 1 centre (-6.5, -26.5) between (-7.5, -26.5) and (-6.5, -27.5) reference; A4 r 1 centre (-6.5, -13.5) between (-6.5, -12.5) and (-7.5, -13.5) reference; A5 r 1 centre (66.742, -24) between (65.91, -23.444) and (66.742, -25) reference; A6 r 3.5 centre (63, -21.5) between (65.91, -23.444) and (63, -18) reference; A7 r 1 centre (57, -17) between (56, -17) and (57, -18) reference; A8 r 1 centre (57, -6.4) between (57, -5.4) and (56, -6.4) reference; A9 r 3.5 centre (63, -1.9) between (63, -5.4) and (63, 1.6) reference; A10 r 1 centre (56.499, 2.6) between (55.571, 2.229) and (56.499, 1.6) reference; A11 r 6 centre (50, 0) between (55.571, 2.229) and (44, 0) reference; A12 r 2 centre (42, -23) between (42, -25) and (44, -23) reference; A13 r 2 centre (11.5, -23) between (9.5, -23) and (11.5, -25) reference; A14 r 2 centre (7.5, -12.5) between (9.5, -12.5) and (7.5, -10.5) reference; A15 r 6 centre (0, 0) between (6, 0) and (-6, 0) reference; A16 r 2 centre (-7.5, -12.5) between (-7.5, -10.5) and (-9.5, -12.5) reference; A17 r 2 centre (-11.5, -23) between (-11.5, -25) and (-9.5, -23) reference; A18 r 2 centre (-7.5, -7.5) between (-7.5, -5.5) and (-9.5, -7.5); A19 r 2 centre (7.5, -7.5) between (9.5, -7.5) and (7.5, -5.5); A20 r 2 centre (-5.5, -9.5) between (-5.5, -7.5) and (-7.5, -9.5); A21 r 2 centre (5.5, -9.5) between (7.5, -9.5) and (5.5, -7.5); 8 further points
  constraints: 14 end point, 8 point on circle, 8 tangent, 6 point on line, 4 centre point, 2 vertical, 1 horizontal, 1 midpoint, 1 perpendicular, 12 other
  dimensions: "d181" = 7 distance from line of L4 point (0, -5.5); "d182" = 2 radius of A19; "d183" = 2 radius of A18; "d184" = 2 radius of A20; "d185" = 2 radius of A21; "d186" = 1 distance between parallel lines of L4 L28
  node "투영된 루프21"
extrude "돌출22" join sketch "스케치21" stored distance "d187" = 10; taper "d188" = 0 deg
extrude "돌출23" cut sketch "스케치21" extent not by distance; stored distance "d189" = 10; taper "d190" = 0 deg
chamfer "모따기2" distance "d191" = 0.5; stored, may be unused: second distance "d192" = 2, angle "d193" = 45 deg
node "작업 평면1"
sketch "스케치22"
  geometry: L1 (-37, 16.5)-(0, 16.5) reference; L2 (5.97, 17.5)-(26, 17.5) reference; L3 (28, 16.5)-(106, 16.5) reference; L4 (96, 12.5)-(96, 20.5); L5 (100, 12.5)-(100, 20.5); L6 (92, 20.5)-(92, 12.5); L7 (108, 13.25)-(108, 7.75) reference; L8 (52, 20.5)-(52, 12.5); L9 (60, 12.5)-(60, 20.5); L10 (56, 12.5)-(56, 20.5); L11 (11.985, 21.8)-(11.985, 14.348); L12 (19.985, 11.991)-(19.985, 21.8); L13 (15.985, 13.2)-(15.985, 21.8); L14 (-29, 20.5)-(-29, 12.5); L15 (-21, 12.5)-(-21, 20.5); L16 (-25, 12.5)-(-25, 20.5); L17 (-29, 14.5)-(-21, 14.5); L18 (11.985, 15.5)-(19.985, 15.5); L19 (52, 14.5)-(60, 14.5); L20 (92, 14.5)-(100, 14.5); C1 r 2 at (96, 20.5); C2 r 2 at (56, 20.5); C3 r 2 at (15.985, 21.8); C4 r 2 at (-25, 20.5); A1 r 4 centre (96, 12.5) between (92, 12.5) and (100, 12.5); A2 r 4 centre (96, 20.5) between (100, 20.5) and (92, 20.5); A3 r 4 centre (56, 20.5) between (60, 20.5) and (52, 20.5); A4 r 4 centre (15.985, 21.8) between (19.985, 21.8) and (11.985, 21.8); A5 r 4 centre (-25, 20.5) between (-21, 20.5) and (-29, 20.5); 7 further points
  constraints: 40 end point, 15 point on line, 10 point on circle, 10 tangent, 9 centre point, 7 perpendicular, 5 midpoint, 4 coincident, 4 parallel, 2 other
  dimensions: "d194" = 4 distance of point (96, 16.5) L4.end; "d195" = 8 diameter of A2; "d196" = 4 diameter of C1; "d197" = 12 distance between parallel lines of L7 L4; "d198" = 8 diameter of A3; "d199" = 4 diameter of C2; "d200" = 8 diameter of A4; "d201" = 4 diameter of C3; "d202" = 8 diameter of A5; "d203" = 4 diameter of C4; "d204" = 40 distance between parallel lines of L4 L10; "d205" = 12 distance of L1.start point (-25, 16.5); "d206" = 2 distance between parallel lines of L20 L3; "d207" = 2 distance between parallel lines of L18 L2
extrude "돌출24" join sketch "스케치22" stored distance "d208" = 4; taper "d209" = 0 deg
sketch "스케치23"
  geometry: L1 (68, 30)-(68, 5); L2 (0, 30)-(78, 30) reference; L3 (28, 30)-(28, 5); L4 (80, 7.75)-(-65, 7.75) reference; L5 (68, 17.5)-(-65, 17.5); L6 (-65, 30)-(-65, 7) reference; L7 (-53, 40)-(-53, -1); L8 (-8.015, 37)-(-16.015, 37) reference; L9 (-8.015, 37)-(-8.015, 41.3) reference; L10 (-16.015, 41.3)-(-16.015, 37) reference; L11 (-12.015, 41.3)-(-12.015, -1); L12 (-2, -1)-(-59, -1) reference; C1 r 2 at (28, 30) reference; C2 r 2 at (68, 30) reference; C3 r 2 at (68, 5) reference; C4 r 2 at (28, 5) reference; C5 r 2 at (-53, 40) reference; C6 r 2 at (-53, 17.5); C7 r 2 at (28, 17.5); C8 r 2 at (68, 17.5); C9 r 2 at (-12.015, 41.3) reference; C10 r 2 at (-12.015, 17.5); A1 r 4 centre (-12.015, 41.3) between (-8.015, 41.3) and (-16.015, 41.3) reference; 2 further points
  constraints: 10 end point, 7 point on line, 4 centre point, 3 perpendicular, 2 coincident, 2 midpoint, 1 vertical
  dimensions: "d210" = 4 diameter of C6; "d211" = 4 diameter of C7; "d212" = 4 diameter of C8; "d213" = 4 diameter of C10
extrude "돌출25" cut sketch "스케치23" distance "d214" = 34; taper "d216" = 0 deg; dims "d215" = 20, "d217" = 0
sketch "스케치24"
  geometry: C1 r 2 at (28, 17.5) reference; 2 further points
  constraints: 1 coincident
hole "구멍3" sketch "스케치24" at (28, 17.5) diameter "d218" = 4; stored, may be unused: countersink angle "d222" = 90 deg, drill point angle "d224" = 118 deg; dims "d219" = 6, "d220" = 6.2, "d221" = 3, "d223" = 8
sketch "스케치25"
  geometry: C1 r 2 at (68, 17.5) reference; 2 further points
  constraints: 1 coincident
hole "구멍4" sketch "스케치25" at (68, 17.5) diameter "d225" = 4; stored, may be unused: countersink angle "d229" = 90 deg, drill point angle "d231" = 118 deg; dims "d226" = 6, "d227" = 6.2, "d228" = 3, "d230" = 8
sketch "스케치26"
  geometry: C1 r 2 at (-25, -2) reference; C2 r 3.1 at (-25, -2); 1 further point
  constraints: 1 centre point, 1 coincident
  dimensions: "d232" = 6.2 diameter of C2
extrude "돌출26" cut sketch "스케치26" distance "d233" = 34; taper "d235" = 0 deg; dims "d234" = 3, "d236" = 0
sketch "스케치27"
  geometry: L1 (20, -12.5)-(0, -12.5) reference; L2 (20, -12.5)-(20, 11.5) reference; L3 (0, 11.5)-(20, 11.5) reference; L4 (0, 0)-(0, 11.5) reference; L5 (0, -12.5)-(0, 0) reference; C1 r 2 at (9.985, -2) reference; C2 r 3.1 at (9.985, -2); 1 further point
  constraints: 1 centre point, 1 coincident
  dimensions: "d237" = 6.2 diameter of C2
extrude "돌출27" cut sketch "스케치27" distance "d238" = 3; taper "d239" = 0 deg
sketch "스케치28"
  geometry: L1 (-53.47, 16)-(-58, 16) reference; L2 (0, 16)-(-53.47, 16) reference; L3 (0, 16)-(0, 0) reference; L4 (20, 0)-(0, 0) reference; L5 (20, 31)-(20, 0) reference; L6 (20, 31)-(-58, 31) reference; L7 (-58, 16)-(-58, 31) reference; C1 r 2 at (-8, 18.5) reference; C2 r 2 at (-48, 18.5) reference; C3 r 6 at (-48, 18.5); C4 r 6 at (-8, 18.5); 1 further point
  constraints: 2 centre point, 2 coincident
  dimensions: "d240" = 12 diameter of C3; "d241" = 12 diameter of C4
extrude "돌출28" cut sketch "스케치28" extent not by distance; stored distance "d242" = 0; taper "d243" = 0 deg
fillet "모깎기7" dims "d244" = 2
sketch "스케치29"
  geometry: L1 (-83.923, 43.982)-(145.526, 43.982); L2 (145.526, 43.982)-(145.526, -44.181); L3 (145.526, -44.181)-(-83.923, -44.181); L4 (-83.923, -44.181)-(-83.923, 43.982); 1 further point
  constraints: 8 end point, 2 parallel, 1 horizontal, 1 perpendicular
extrude "돌출29" cut sketch "스케치29" extent not by distance; stored distance "d245" = 0; taper "d246" = 0 deg
chamfer "모따기3" distance "d247" = 4; stored, may be unused: second distance "d248" = 2, angle "d249" = 45 deg
sketch "스케치30"
  geometry: C1 r 4.4 at (13, 18) reference; C2 r 5 at (13, 18); 1 further point
  constraints: 1 centre point, 1 coincident
  dimensions: "d250" = 10 diameter of C2
extrude "돌출30" cut sketch "스케치30" extent not by distance; stored distance "d251" = 0; taper "d252" = 0 deg
sketch "스케치31"
  geometry: C1 r 11.3 at (0, 0) reference; C2 r 2 at (0, 8) reference; C3 r 2 at (8, 0) reference; C4 r 2 at (0, -8) reference; C5 r 2 at (-8, 0) reference; C6 r 5.25 at (0, 0) reference; C7 r 11.8 at (0, 0); C8 r 5.55 at (0, 0); 1 further point
  constraints: 2 centre point, 2 coincident
  dimensions: "d253" = 0.3 radial gap between concentric circles of C8 C6; "d254" = 0.5 radial gap between concentric circles of C1 C7
  node "투영된 루프25"
extrude "돌출31" cut sketch "스케치31" extent not by distance; stored distance "d255" = 0; taper "d256" = 0 deg
extrude "돌출32" cut sketch "스케치31" extent not by distance; stored distance "d257" = 0; taper "d258" = 0 deg
node "솔리드1"
node "투영된 루프1"
node "투영된 루프2"
node "투영된 루프3"
node "투영된 루프4"
node "투영된 루프5"
node "투영된 루프6"
node "투영된 루프7"
node "투영된 루프8"
node "투영된 루프9"
node "투영된 루프10"
node "투영된 루프11"
node "투영된 루프12"
node "투영된 루프13"
node "투영된 루프14"
node "투영된 루프15"
node "투영된 루프16"
node "투영된 루프19"
node "투영된 루프20"
node "투영된 루프22"
node "투영된 루프23"
node "투영된 루프24"
feature "A9D066F2-1C7D-4E18-AEED-F7BC21143FA4" dims "d88" = 4, "d89" = 6, "d90" = 6.2, "d91" = 4, "d92" = 90 deg, "d93" = 8, "d94" = 0
